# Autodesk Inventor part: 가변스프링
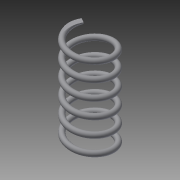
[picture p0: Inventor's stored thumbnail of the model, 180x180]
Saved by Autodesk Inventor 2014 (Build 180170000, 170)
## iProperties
Created: 2016-12
Part Number: 가변스프링
Material: Generic
Document SubType Name: Modeling
Designer: user
Density: 1 g/cm^3
Appearance: Default
Author: user
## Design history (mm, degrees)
sketch "Sketch1"
  geometry: L1 (0, 0)-(7.5, 0); L2 (7.5, 0)-(7.5, 35); L3 (7.5, 35)-(0, 35); L4 (0, 35)-(0, 0); C1 r 1 at (7.5, 0)
  constraints: 8 end point, 2 parallel, 1 centre point, 1 coincident, 1 horizontal, 1 perpendicular
  dimensions: "d0" = 15 diameter of L2 L4; "d1" = 35 distance between parallel lines of L3 L1 (derived); "d2" = 1 radius of C1
coil "Coil1" sketch "Sketch1" pitch "d3" = 6; turns "d5" = 1; dims "d4" = 35 (= d1), "d6" = 0, angle "d7" = 90 deg, angle "d8" = 90 deg, "d9" = 0, "d10" = 0
sketch "Sketch2"
  geometry: L1 (0, 6.5)-(0, 8.5) reference; 1 further point
  constraints: 1 vertical alignment
extrude "Extrusion1" cut sketch "Sketch2" distance "d11" = 10; taper "d12" = 0 deg
workplane "Work Plane1"
sketch "Sketch3"
  geometry: L1 (5.629, 3.25)-(7.361, 4.25) reference; 1 further point
  constraints: 1 other
extrude "Extrusion2" cut sketch "Sketch3" distance "d13" = 10; taper "d14" = 0 deg
body "Solid1"
node "Project Cut Edges1"
node "Project Cut Edges2"
